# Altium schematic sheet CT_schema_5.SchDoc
size 562 x 419 mm
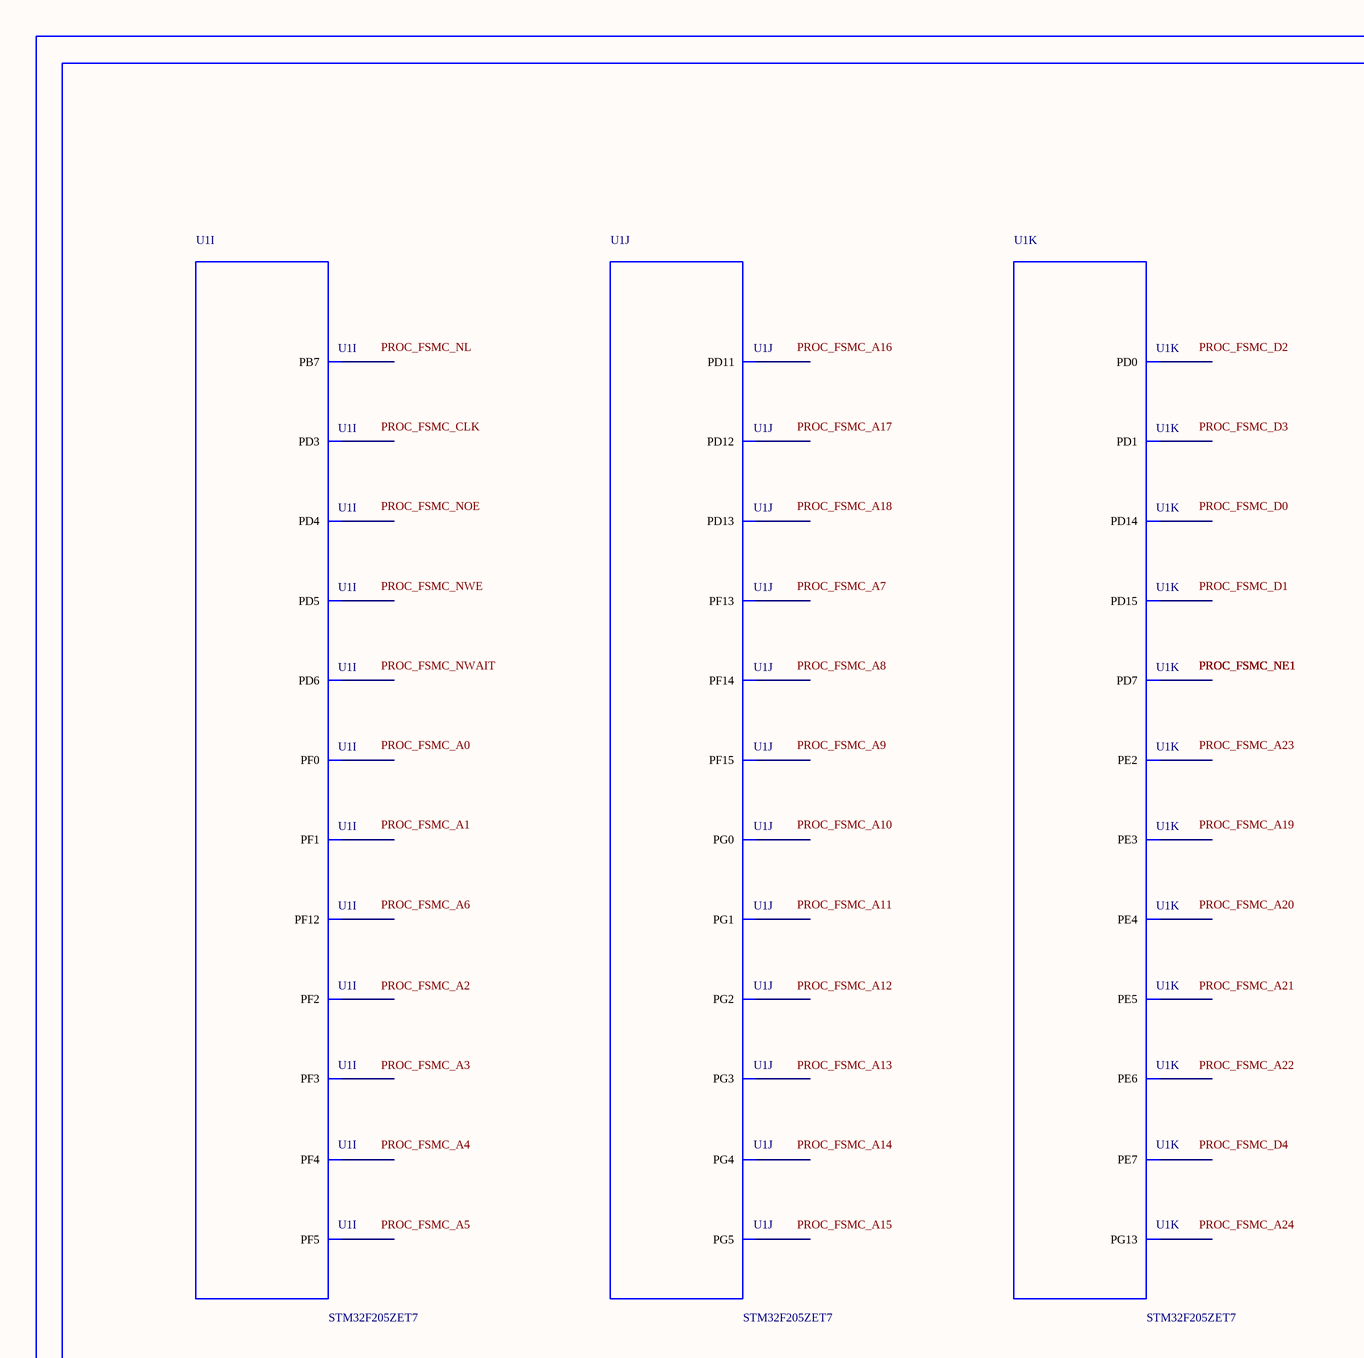
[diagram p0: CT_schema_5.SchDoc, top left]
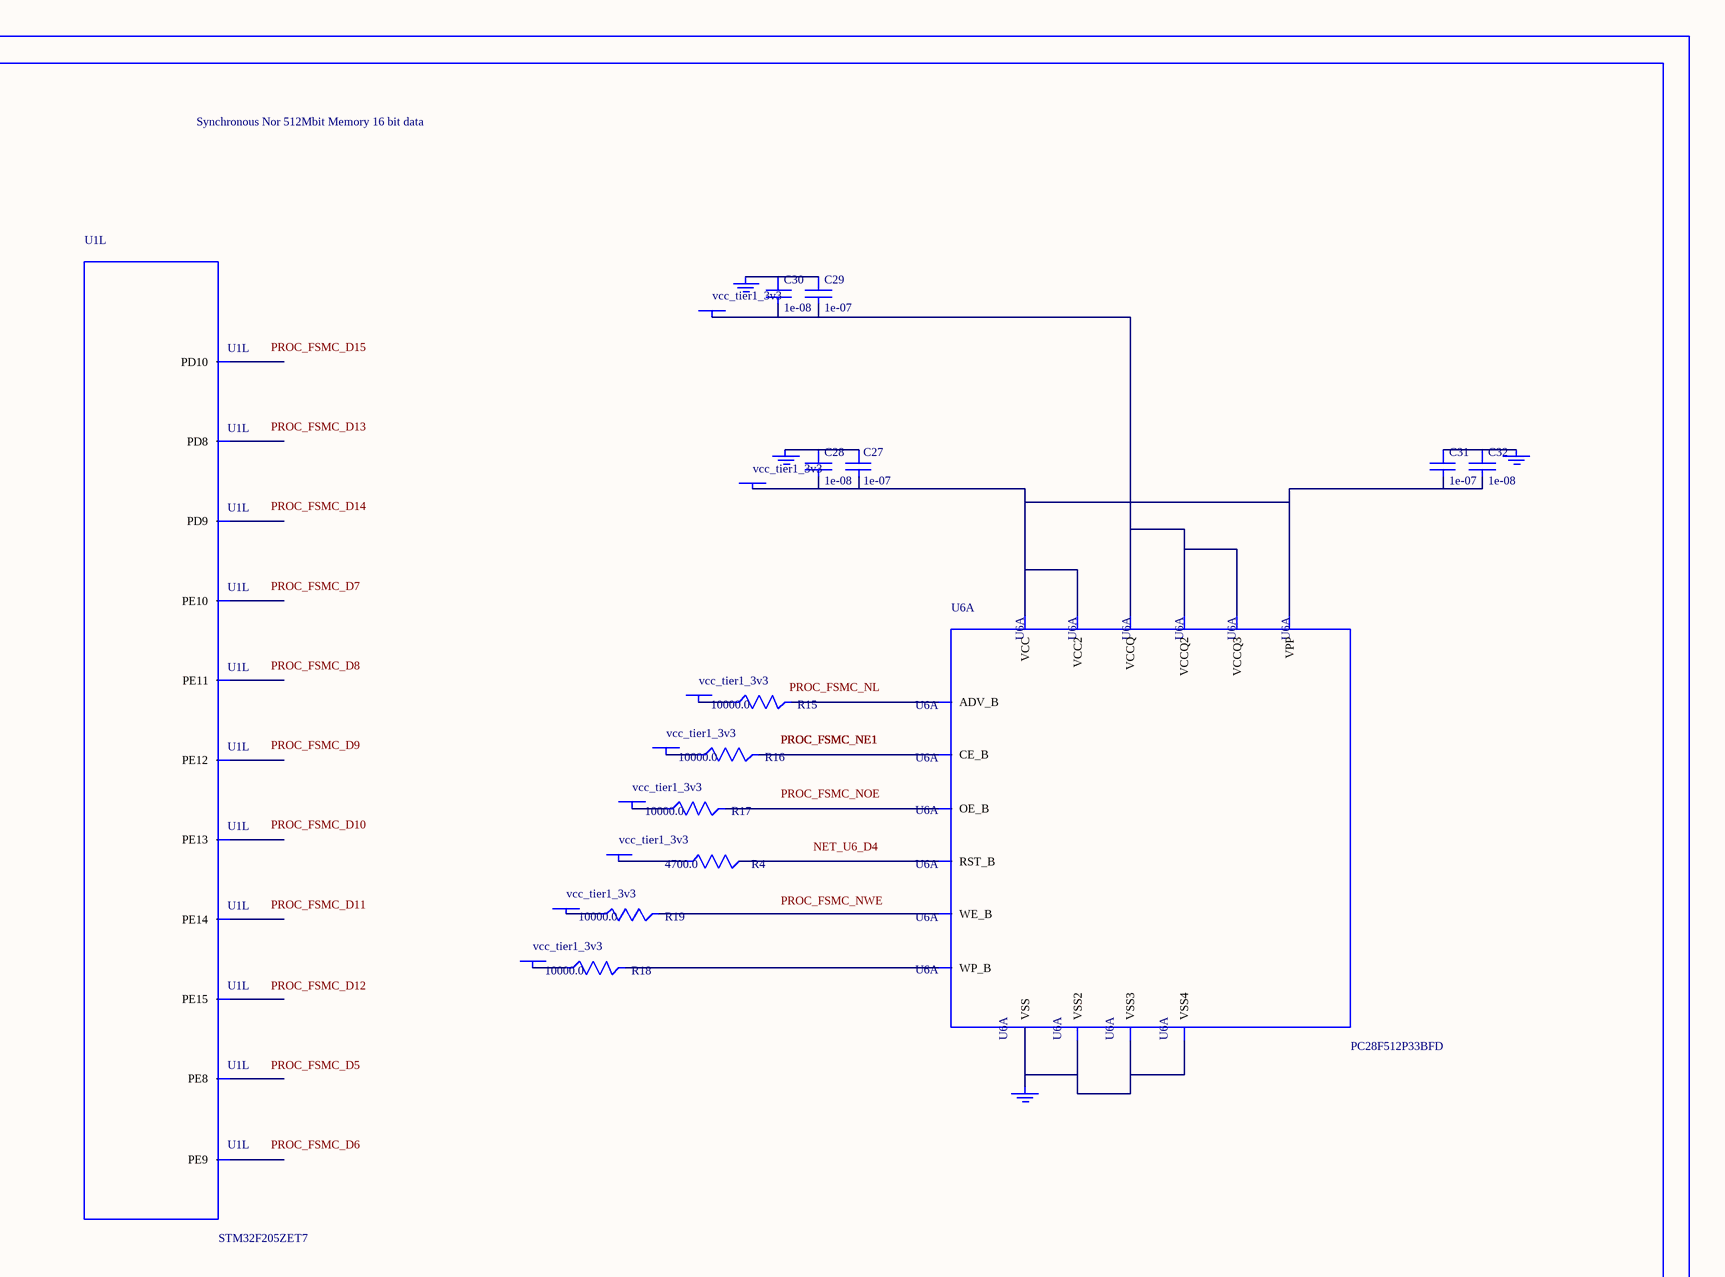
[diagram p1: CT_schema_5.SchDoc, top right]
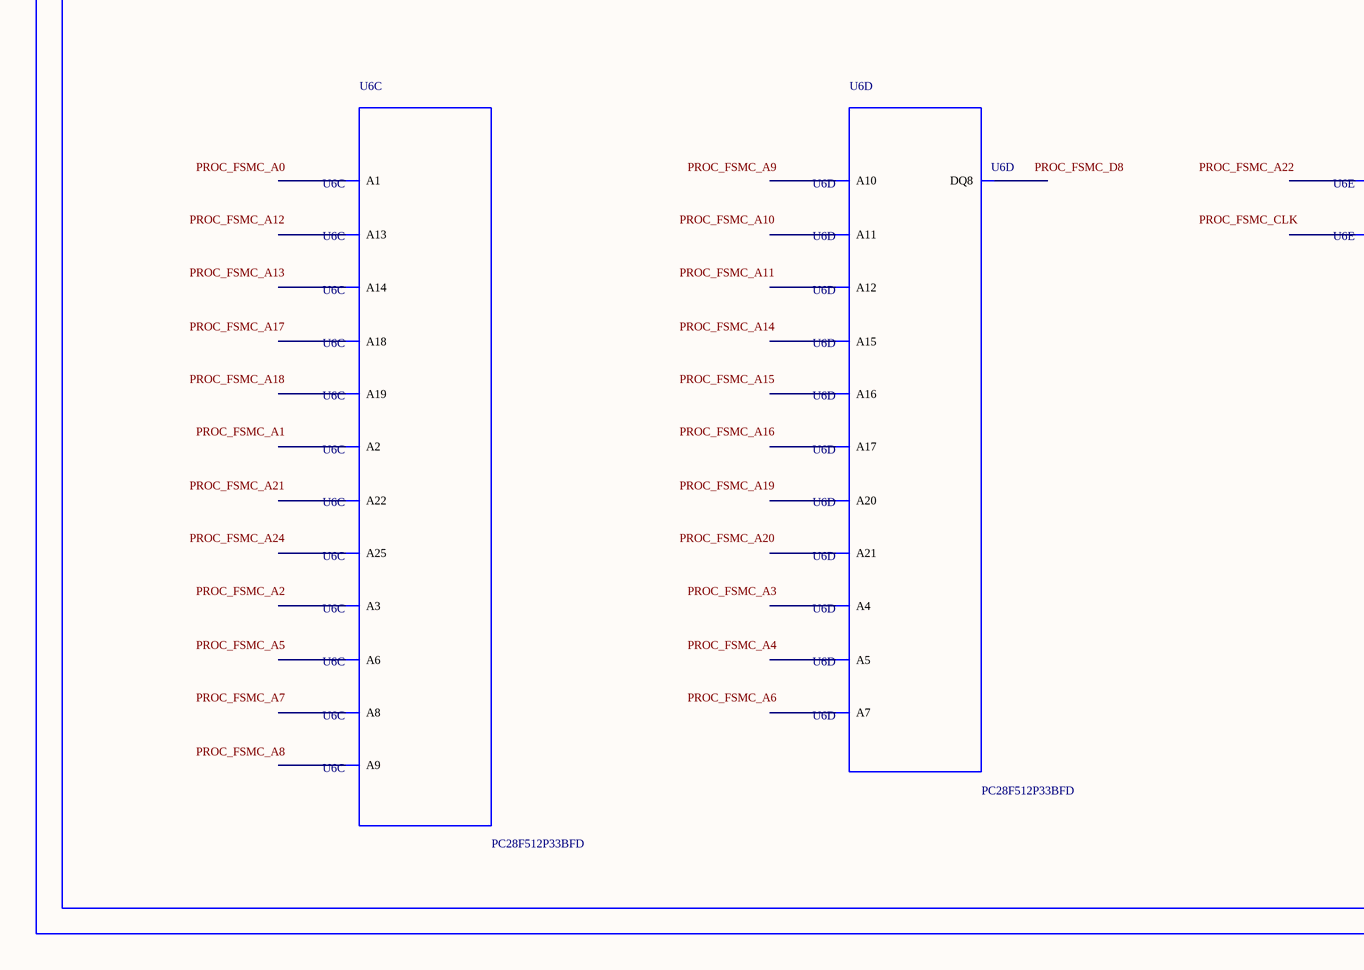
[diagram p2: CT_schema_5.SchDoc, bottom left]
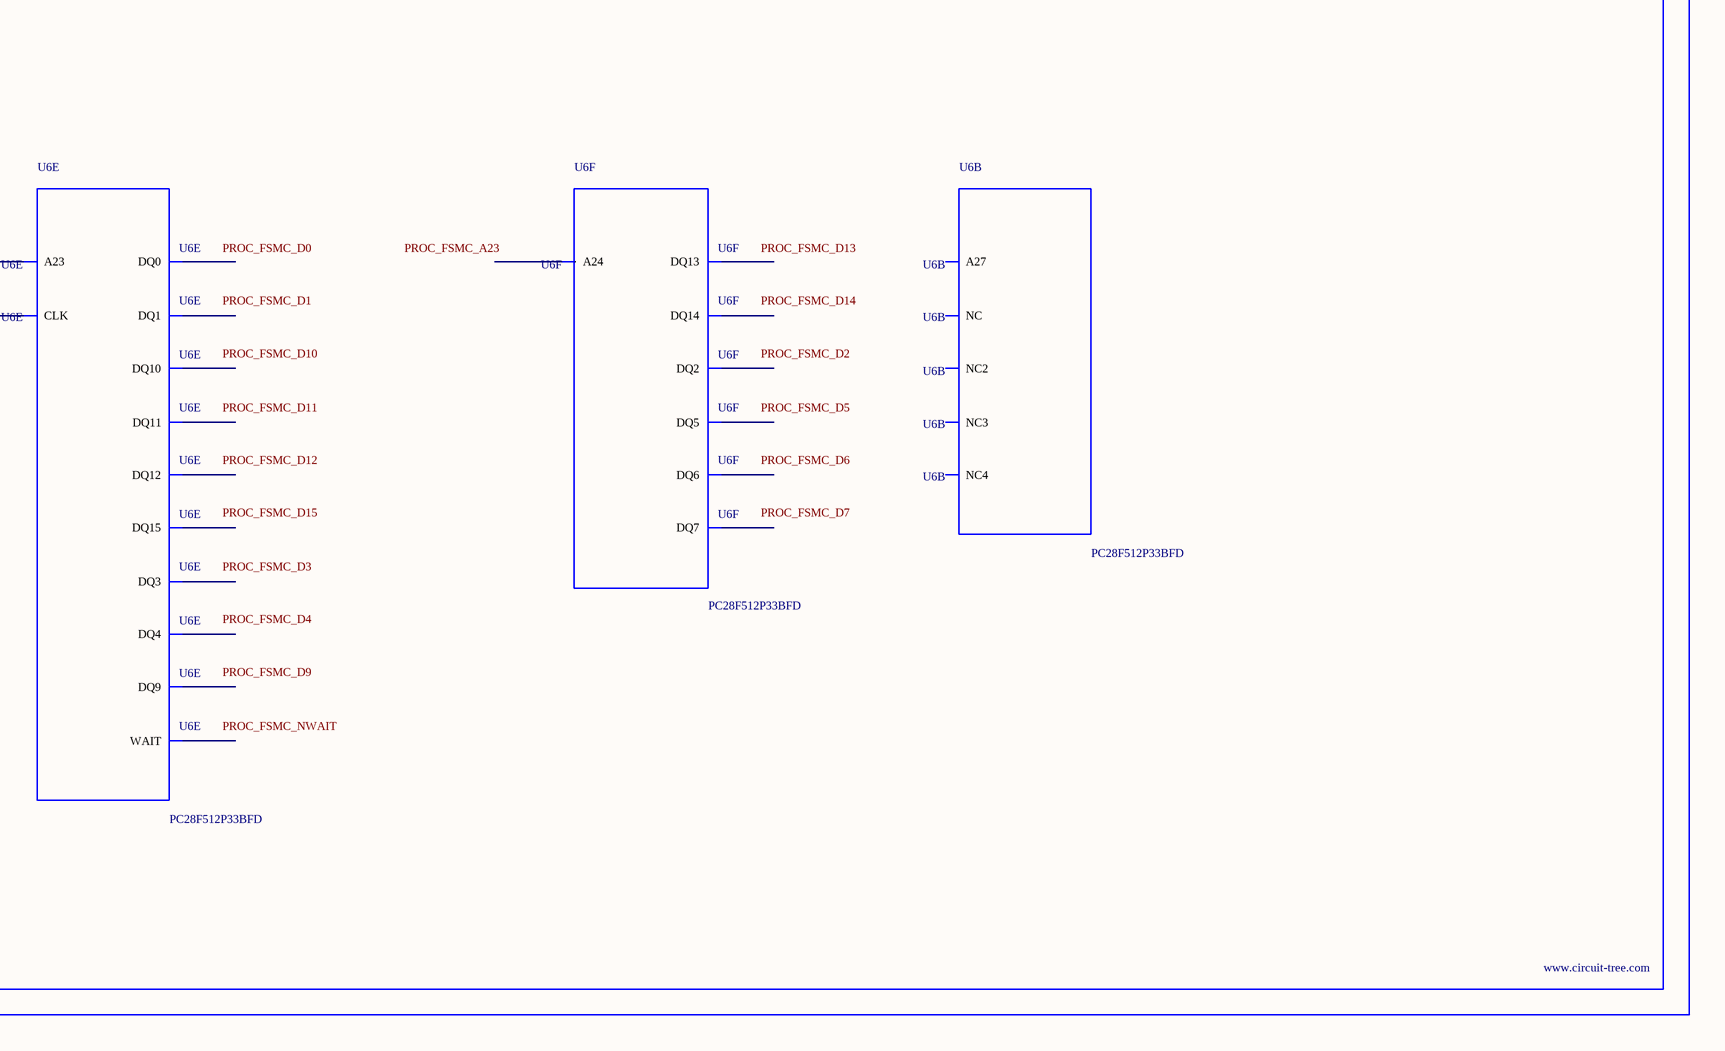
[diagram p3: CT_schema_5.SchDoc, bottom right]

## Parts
BORDER4  (no value)
C27  1e-07  [C0402]
C28  1e-08  [C0402]
C29  1e-07  [C0402]
C30  1e-08  [C0402]
C31  1e-07  [C0402]
C32  1e-08  [C0402]
GND_INSTANCE_4_0  (no value)
GND_INSTANCE_4_1  (no value)
GND_INSTANCE_4_2  (no value)
GND_INSTANCE_4_3  (no value)
POWER_INSTANCE_4_0  vcc_tier1_3v3
POWER_INSTANCE_4_1  vcc_tier1_3v3
POWER_INSTANCE_4_2  vcc_tier1_3v3
POWER_INSTANCE_4_3  vcc_tier1_3v3
POWER_INSTANCE_4_4  vcc_tier1_3v3
POWER_INSTANCE_4_5  vcc_tier1_3v3
POWER_INSTANCE_4_6  vcc_tier1_3v3
POWER_INSTANCE_4_7  vcc_tier1_3v3
R4  4700.0  [R0603]
R15  10000.0  [R0603]
R16  10000.0  [R0603]
R17  10000.0  [R0603]
R18  10000.0  [R0603]
R19  10000.0  [R0603]
U1  STM32F205ZET7  [LQFP144]  (parts I,J,K,L of 13)
U6  PC28F512P33BFD  [PC28F512P33BFD]  (parts A,B,C,D,E,F of 6)

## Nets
NetC27_1: C27.1 C28.1 GND_INSTANCE_4_0.0(GND)
NetC27_2: C27.2 C28.2 C31.2 C32.2 POWER_INSTANCE_4_0.0(PWR) U6.A4(VPP) U6.A6(VCC) U6.H3(VCC2)
NetC29_1: C29.1 C30.1 GND_INSTANCE_4_1.0(GND)
NetC29_2: C29.2 C30.2 POWER_INSTANCE_4_1.0(PWR) U6.D5(VCCQ) U6.D6(VCCQ2) U6.G4(VCCQ3)
NetC31_1: C31.1 C32.1 GND_INSTANCE_4_2.0(GND)
NetGND_INSTANCE_4_3_0: GND_INSTANCE_4_3.0(GND) U6.B2(VSS) U6.H2(VSS2) U6.H4(VSS3) U6.H6(VSS4)
NetPOWER_INSTANCE_4_2_0: POWER_INSTANCE_4_2.0(PWR) R15.1
NetPOWER_INSTANCE_4_3_0: POWER_INSTANCE_4_3.0(PWR) R16.1
NetPOWER_INSTANCE_4_4_0: POWER_INSTANCE_4_4.0(PWR) R17.1
NetPOWER_INSTANCE_4_5_0: POWER_INSTANCE_4_5.0(PWR) R18.1
NetPOWER_INSTANCE_4_6_0: POWER_INSTANCE_4_6.0(PWR) R19.1
NetPOWER_INSTANCE_4_7_0: POWER_INSTANCE_4_7.0(PWR) R4.1
NetR4_2: R4.2 U6.D4(RST_B)
NetR15_2: R15.2 U6.F6(ADV_B)
NetR16_2: R16.2 U6.B4(CE_B)
NetR17_2: R17.2 U6.F8(OE_B)
NetR18_2: R18.2 U6.C6(WP_B)
NetR19_2: R19.2 U6.G8(WE_B)

Not connected (* = marked no-connect by the designer): U1 1(PE2) 2(PE3) 3(PE4) 4(PE5) 5(PE6) 10(PF0) 11(PF1) 12(PF2) 13(PF3) 14(PF4) 15(PF5) 50(PF12) 53(PF13) 54(PF14) 55(PF15) 56(PG0) 57(PG1) 58(PE7) 59(PE8) 60(PE9) 63(PE10) 64(PE11) 65(PE12) 66(PE13) 67(PE14) 68(PE15) 77(PD8) 78(PD9) 79(PD10) 80(PD11) 81(PD12) 82(PD13) 85(PD14) 86(PD15) 87(PG2) 88(PG3) 89(PG4) 90(PG5) 114(PD0) 115(PD1) 117(PD3) 118(PD4) 119(PD5) 122(PD6) 123(PD7) 128(PG13) 137(PB7); U6 A1 A2(A6) A3(A8) A5(A13) A7(A18) A8(A22) B1(A2) B3(A9) B5(A14) B6(A25) B7(A19) B8(NC) C1(A3) C2(A7) C3(A10) C4(A12) C5(A15) C7(A20) C8(A21) D1(A4) D2(A5) D3(A11) D7(A16) D8(A17) E1(DQ8) E2(DQ1) E3(DQ9) E4(DQ3) E5(DQ4) E6(CLK) E7(DQ15) E8(NC2) F1(NC3) F2(DQ0) F3(DQ10) F4(DQ11) F5(DQ12) F7(WAIT) G1(A23) G2(NC4) G3(DQ2) G5(DQ5) G6(DQ6) G7(DQ14) H1(A27) H5(DQ13) H7(DQ7) H8(A24)

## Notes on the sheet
- Labels drawn without touching a wire or pin: NET_U6_D4, PROC_FSMC_A0, PROC_FSMC_A1, PROC_FSMC_A2, PROC_FSMC_A3, PROC_FSMC_A4, PROC_FSMC_A5, PROC_FSMC_A6, PROC_FSMC_A7, PROC_FSMC_A8, PROC_FSMC_A9, PROC_FSMC_A10, PROC_FSMC_A11, PROC_FSMC_A12, PROC_FSMC_A13, PROC_FSMC_A14, PROC_FSMC_A15, PROC_FSMC_A16, PROC_FSMC_A17, PROC_FSMC_A18, PROC_FSMC_A19, PROC_FSMC_A20, PROC_FSMC_A21, PROC_FSMC_A22, PROC_FSMC_A23, PROC_FSMC_A24, PROC_FSMC_CLK, PROC_FSMC_D0, PROC_FSMC_D1, PROC_FSMC_D2, PROC_FSMC_D3, PROC_FSMC_D4, PROC_FSMC_D5, PROC_FSMC_D6, PROC_FSMC_D7, PROC_FSMC_D8, PROC_FSMC_D9, PROC_FSMC_D10, PROC_FSMC_D11, PROC_FSMC_D12, PROC_FSMC_D13, PROC_FSMC_D14, PROC_FSMC_D15, PROC_FSMC_NL, PROC_FSMC_NOE, PROC_FSMC_NWAIT, PROC_FSMC_NWE

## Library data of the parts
BORDER4 = BORDER_PAGE4
C27 C29 C31 = C0402C104K3RACTU
C28 C30 C32 = C0402C103K3RAC
GND_INSTANCE_4_0-GND_INSTANCE_4_3 = GND
POWER_INSTANCE_4_0-POWER_INSTANCE_4_7 = PWR
R4 = RC0603JR-074K7L
R15-R19 = RC0603JR-0710KL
